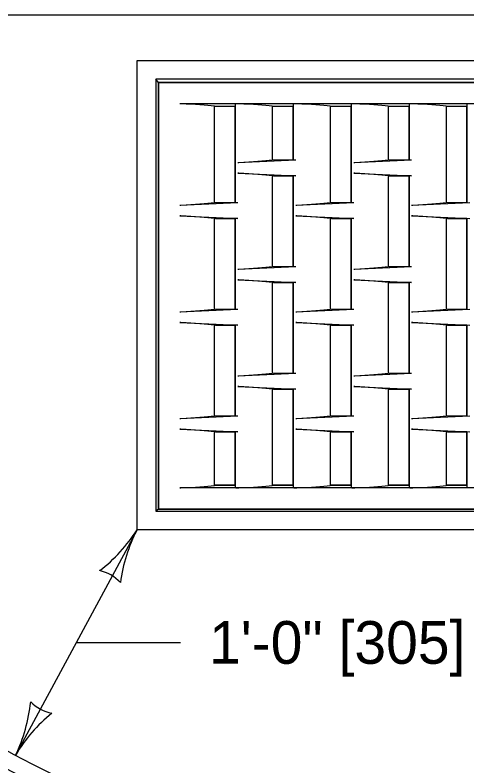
# Model space of a CAD drawing. Extents: x 49991.4 to 50021, y 49987.6 to 50011.4.
# Drawn here: x 50012.78 to 50013.415, y 49997.26 to 49998.316 of the extents above; entities that cross this region are included whole.
import ezdxf

# ---------------------------------------------------------------- set-up
doc = ezdxf.new("R2010")
doc.units = 0
for name, color, linetype in [('Level 1', 7, 'Continuous'), ('Level 18', 7, 'Continuous'), ('Level 2', 7, 'Continuous'), ('Level 3', 7, 'Continuous')]:
    doc.layers.add(name, color=color, linetype=linetype)

msp = doc.modelspace()

# ---------------------------------------------------------------- linework, layer by layer
at = {"layer": 'Level 1'}
for p, q in [((50014.5233, 49998.3155), (50012.1592, 49998.3155)), ((50012.9512, 49997.5919), (50012.9512, 49998.2518)), ((50012.9512, 49998.2518), (50013.7313, 49998.2518)), ((50012.9775, 49998.2255), (50012.9775, 49997.6182)), ((50012.9812, 49998.2207), (50012.9775, 49998.2255)), ((50013.705, 49998.2255), (50012.9775, 49998.2255)), ((50013.7013, 49998.2207), (50012.9812, 49998.2207)), ((50013.6612, 49998.1907), (50013.0112, 49998.1907)), ((50013.0599, 49998.1874), (50013.0599, 49998.0535)), ((50013.089, 49998.1869), (50013.0599, 49998.1869)), ((50013.089, 49998.1904), (50013.089, 49998.0519)), ((50013.1414, 49998.1874), (50013.1414, 49998.1869)), ((50013.1706, 49998.1869), (50013.1414, 49998.1869)), ((50013.1414, 49998.1869), (50013.1414, 49998.1135)), ((50013.1706, 49998.1904), (50013.1706, 49998.1119)), ((50013.2229, 49998.1874), (50013.2229, 49998.1869)), ((50013.2521, 49998.1869), (50013.2229, 49998.1869)), ((50013.2229, 49998.1869), (50013.2229, 49998.0535)), ((50013.2521, 49998.1904), (50013.2521, 49998.0519)), ((50013.3045, 49998.1874), (50013.3045, 49998.1869)), ((50013.3337, 49998.1869), (50013.3045, 49998.1869)), ((50013.3045, 49998.1869), (50013.3045, 49998.1135)), ((50013.3337, 49998.1904), (50013.3337, 49998.1119)), ((50013.386, 49998.1874), (50013.386, 49998.1869)), ((50013.4152, 49998.1869), (50013.386, 49998.1869)), ((50013.386, 49998.1869), (50013.386, 49998.0535)), ((50013.4152, 49998.1904), (50013.4152, 49998.0519)), ((50013.0928, 49998.1082), (50013.1743, 49998.1119)), ((50013.143, 49998.1119), (50013.1706, 49998.1119)), ((50013.2559, 49998.1082), (50013.3374, 49998.1119)), ((50013.306, 49998.1119), (50013.3337, 49998.1119)), ((50013.0928, 49998.0932), (50013.1743, 49998.0894)), ((50013.143, 49998.0894), (50013.1706, 49998.0894)), ((50013.1706, 49998.0895), (50013.1706, 49997.9619)), ((50013.2559, 49998.0932), (50013.3374, 49998.0894)), ((50013.306, 49998.0894), (50013.3337, 49998.0894)), ((50013.3337, 49998.0895), (50013.3337, 49997.9619)), ((50013.1414, 49998.0879), (50013.1414, 49997.9635)), ((50013.3045, 49998.0879), (50013.3045, 49997.9635)), ((50013.0112, 49998.0482), (50013.0928, 49998.052)), ((50013.0614, 49998.052), (50013.089, 49998.052)), ((50013.1743, 49998.0482), (50013.2559, 49998.052)), ((50013.2245, 49998.052), (50013.2521, 49998.052)), ((50013.3374, 49998.0482), (50013.419, 49998.052)), ((50013.3876, 49998.052), (50013.4152, 49998.052)), ((50013.0112, 49998.0332), (50013.0928, 49998.0295)), ((50013.0599, 49998.0279), (50013.0599, 49997.9036)), ((50013.0614, 49998.0295), (50013.089, 49998.0295)), ((50013.089, 49998.0295), (50013.089, 49997.902)), ((50013.1743, 49998.0332), (50013.2559, 49998.0295)), ((50013.2229, 49998.0279), (50013.2229, 49997.9036)), ((50013.2245, 49998.0295), (50013.2521, 49998.0295)), ((50013.2521, 49998.0295), (50013.2521, 49997.902)), ((50013.3374, 49998.0332), (50013.419, 49998.0295)), ((50013.386, 49998.0279), (50013.386, 49997.9036)), ((50013.3876, 49998.0295), (50013.4152, 49998.0295)), ((50013.4152, 49998.0295), (50013.4152, 49997.902)), ((50013.0928, 49997.9582), (50013.1743, 49997.962)), ((50013.143, 49997.962), (50013.1706, 49997.962)), ((50013.2559, 49997.9582), (50013.3374, 49997.962)), ((50013.306, 49997.962), (50013.3337, 49997.962)), ((50013.0928, 49997.9432), (50013.1743, 49997.9395)), ((50013.2559, 49997.9432), (50013.3374, 49997.9395)), ((50013.1414, 49997.9379), (50013.1414, 49997.8136)), ((50013.143, 49997.9395), (50013.1706, 49997.9395)), ((50013.1706, 49997.9395), (50013.1706, 49997.812)), ((50013.3045, 49997.9379), (50013.3045, 49997.8136)), ((50013.306, 49997.9395), (50013.3337, 49997.9395)), ((50013.3337, 49997.9395), (50013.3337, 49997.812)), ((50013.0112, 49997.8982), (50013.0928, 49997.902)), ((50013.0614, 49997.902), (50013.089, 49997.902)), ((50013.1743, 49997.8982), (50013.2559, 49997.902)), ((50013.2245, 49997.902), (50013.2521, 49997.902)), ((50013.3374, 49997.8982), (50013.419, 49997.902)), ((50013.3876, 49997.902), (50013.4152, 49997.902)), ((50013.0112, 49997.8832), (50013.0928, 49997.8795)), ((50013.0599, 49997.8779), (50013.0599, 49997.7536)), ((50013.0614, 49997.8795), (50013.089, 49997.8795)), ((50013.089, 49997.8795), (50013.089, 49997.752)), ((50013.1743, 49997.8832), (50013.2559, 49997.8795)), ((50013.2229, 49997.8779), (50013.2229, 49997.7536)), ((50013.2245, 49997.8795), (50013.2521, 49997.8795)), ((50013.2521, 49997.8795), (50013.2521, 49997.752)), ((50013.3374, 49997.8832), (50013.419, 49997.8795)), ((50013.386, 49997.8779), (50013.386, 49997.7536)), ((50013.3876, 49997.8795), (50013.4152, 49997.8795)), ((50013.4152, 49997.8795), (50013.4152, 49997.752)), ((50013.0928, 49997.8083), (50013.1743, 49997.812)), ((50013.143, 49997.812), (50013.1706, 49997.812)), ((50013.2559, 49997.8083), (50013.3374, 49997.812)), ((50013.306, 49997.812), (50013.3337, 49997.812)), ((50013.0928, 49997.7933), (50013.1743, 49997.7895)), ((50013.2559, 49997.7933), (50013.3374, 49997.7895)), ((50013.1414, 49997.788), (50013.1414, 49997.6546)), ((50013.143, 49997.7895), (50013.1706, 49997.7895)), ((50013.1706, 49997.7896), (50013.1706, 49997.6511)), ((50013.3045, 49997.788), (50013.3045, 49997.6546)), ((50013.306, 49997.7895), (50013.3337, 49997.7895)), ((50013.3337, 49997.7896), (50013.3337, 49997.6511)), ((50013.0112, 49997.7483), (50013.0928, 49997.752)), ((50013.0614, 49997.752), (50013.089, 49997.752)), ((50013.1743, 49997.7483), (50013.2559, 49997.752)), ((50013.2245, 49997.752), (50013.2521, 49997.752)), ((50013.3374, 49997.7483), (50013.419, 49997.752)), ((50013.3876, 49997.752), (50013.4152, 49997.752)), ((50013.0112, 49997.7333), (50013.0928, 49997.7295)), ((50013.0614, 49997.7295), (50013.089, 49997.7295)), ((50013.089, 49997.7296), (50013.089, 49997.6511)), ((50013.1743, 49997.7333), (50013.2559, 49997.7295)), ((50013.2245, 49997.7295), (50013.2521, 49997.7295)), ((50013.2521, 49997.7296), (50013.2521, 49997.6511)), ((50013.3374, 49997.7333), (50013.419, 49997.7295)), ((50013.3876, 49997.7295), (50013.4152, 49997.7295)), ((50013.4152, 49997.7296), (50013.4152, 49997.6511)), ((50013.0599, 49997.728), (50013.0599, 49997.6541)), ((50013.2229, 49997.728), (50013.2229, 49997.6546)), ((50013.386, 49997.728), (50013.386, 49997.6546)), ((50013.6612, 49997.6508), (50013.0112, 49997.6508)), ((50013.089, 49997.6546), (50013.0599, 49997.6546)), ((50013.1706, 49997.6546), (50013.1414, 49997.6546)), ((50013.1414, 49997.6546), (50013.1414, 49997.6541)), ((50013.2521, 49997.6546), (50013.2229, 49997.6546)), ((50013.2229, 49997.6546), (50013.2229, 49997.6541)), ((50013.3337, 49997.6546), (50013.3045, 49997.6546)), ((50013.3045, 49997.6546), (50013.3045, 49997.6541)), ((50013.4152, 49997.6546), (50013.386, 49997.6546)), ((50013.386, 49997.6546), (50013.386, 49997.6541)), ((50012.9812, 49997.6208), (50012.9775, 49997.6182)), ((50012.9775, 49997.6182), (50013.705, 49997.6182)), ((50012.9812, 49997.6208), (50013.7013, 49997.6208)), ((50013.7313, 49997.5919), (50012.9512, 49997.5919))]:
    msp.add_line(p, q, dxfattribs=at)
msp.add_lwpolyline([(50012.9812, 49998.2207), (50013.7011, 49998.2207), (50013.7011, 49997.6208), (50012.9812, 49997.6208)], close=True, dxfattribs=at)
for points in [[(50013.0599, 49998.1869), (50013.0599, 49998.0535)], [(50013.0614, 49998.052), (50013.089, 49998.052), (50013.089, 49998.1869), (50013.0599, 49998.1869)], [(50013.1706, 49998.1119), (50013.1706, 49998.1869), (50013.1414, 49998.1869), (50013.1414, 49998.1135)], [(50013.2521, 49998.052), (50013.2521, 49998.1869), (50013.2229, 49998.1869), (50013.2229, 49998.0535)], [(50013.3337, 49998.1119), (50013.3337, 49998.1869), (50013.3045, 49998.1869), (50013.3045, 49998.1135)], [(50013.4152, 49998.052), (50013.4152, 49998.1869), (50013.386, 49998.1869), (50013.386, 49998.0535)], [(50013.143, 49998.1119), (50013.1706, 49998.1119)], [(50013.306, 49998.1119), (50013.3337, 49998.1119)], [(50013.1706, 49997.962), (50013.1706, 49998.0894), (50013.143, 49998.0894)], [(50013.1414, 49998.0879), (50013.1414, 49997.9635)], [(50013.2245, 49998.052), (50013.2521, 49998.052)], [(50013.3876, 49998.052), (50013.4152, 49998.052)], [(50013.0599, 49998.0279), (50013.0599, 49997.9036)], [(50013.089, 49997.902), (50013.089, 49998.0295), (50013.0614, 49998.0295)], [(50013.2229, 49998.0279), (50013.2229, 49997.9036)], [(50013.2521, 49997.902), (50013.2521, 49998.0295), (50013.2245, 49998.0295)], [(50013.386, 49998.0279), (50013.386, 49997.9036)], [(50013.4152, 49997.902), (50013.4152, 49998.0295), (50013.3876, 49998.0295)], [(50013.143, 49997.962), (50013.1706, 49997.962)], [(50013.1414, 49997.9379), (50013.1414, 49997.8136)], [(50013.1706, 49997.812), (50013.1706, 49997.9395), (50013.143, 49997.9395)], [(50013.0614, 49997.902), (50013.089, 49997.902)], [(50013.2245, 49997.902), (50013.2521, 49997.902)], [(50013.3876, 49997.902), (50013.4152, 49997.902)], [(50013.0599, 49997.8779), (50013.0599, 49997.7536)], [(50013.089, 49997.752), (50013.089, 49997.8795), (50013.0614, 49997.8795)], [(50013.2229, 49997.8779), (50013.2229, 49997.7536)], [(50013.2521, 49997.752), (50013.2521, 49997.8795), (50013.2245, 49997.8795)], [(50013.143, 49997.812), (50013.1706, 49997.812)], [(50013.1414, 49997.788), (50013.1414, 49997.6546), (50013.1706, 49997.6546)], [(50013.1706, 49997.6546), (50013.1706, 49997.7895), (50013.143, 49997.7895)], [(50013.3045, 49997.788), (50013.3045, 49997.6546), (50013.3337, 49997.6546)], [(50013.3337, 49997.6546), (50013.3337, 49997.7895), (50013.306, 49997.7895)], [(50013.0614, 49997.752), (50013.089, 49997.752)], [(50013.2245, 49997.752), (50013.2521, 49997.752)], [(50013.2521, 49997.6546), (50013.2521, 49997.7295), (50013.2245, 49997.7295)], [(50013.2229, 49997.728), (50013.2229, 49997.6546), (50013.2521, 49997.6546)]]:
    msp.add_lwpolyline(points, dxfattribs=at)
for centre, radius, start, end in [((50013.3412, 49998.3155), 1.2045, 180, 0), ((50013.3412, 49998.3155), 1.182, 180, 0), ((50013.143, 49998.1135), 0.00156, 180, 270), ((50013.143, 49998.1135), 0.00156, 180, 270), ((50013.306, 49998.1135), 0.00156, 180, 270), ((50013.306, 49998.1135), 0.00156, 180, 270), ((50013.143, 49998.0879), 0.00156, 90, 180), ((50013.143, 49998.0879), 0.00156, 90, 180), ((50013.306, 49998.0879), 0.00156, 90, 180), ((50013.0614, 49998.0535), 0.00156, 180, 270), ((50013.0614, 49998.0535), 0.00156, 180, 270), ((50013.2245, 49998.0535), 0.00156, 180, 270), ((50013.2245, 49998.0535), 0.00156, 180, 270), ((50013.3876, 49998.0535), 0.00156, 180, 270), ((50013.3876, 49998.0535), 0.00156, 180, 270), ((50013.0614, 49998.0279), 0.00156, 90, 180), ((50013.0614, 49998.0279), 0.00156, 90, 180), ((50013.2245, 49998.0279), 0.00156, 90, 180), ((50013.2245, 49998.0279), 0.00156, 90, 180), ((50013.3876, 49998.0279), 0.00156, 90, 180), ((50013.3876, 49998.0279), 0.00156, 90, 180), ((50013.143, 49997.9635), 0.00156, 180, 270), ((50013.143, 49997.9635), 0.00156, 180, 270), ((50013.306, 49997.9635), 0.00156, 180, 270), ((50013.143, 49997.9379), 0.00156, 90, 180), ((50013.143, 49997.9379), 0.00156, 90, 180), ((50013.306, 49997.9379), 0.00156, 90, 180), ((50013.0614, 49997.9036), 0.00156, 180, 270), ((50013.0614, 49997.9036), 0.00156, 180, 270), ((50013.2245, 49997.9036), 0.00156, 180, 270), ((50013.2245, 49997.9036), 0.00156, 180, 270), ((50013.3876, 49997.9036), 0.00156, 180, 270), ((50013.3876, 49997.9036), 0.00156, 180, 270), ((50013.0614, 49997.8779), 0.00156, 90, 180), ((50013.0614, 49997.8779), 0.00156, 90, 180), ((50013.2245, 49997.8779), 0.00156, 90, 180), ((50013.2245, 49997.8779), 0.00156, 90, 180), ((50013.3876, 49997.8779), 0.00156, 90, 180), ((50013.143, 49997.8136), 0.00156, 180, 270), ((50013.143, 49997.8136), 0.00156, 180, 270), ((50013.306, 49997.8136), 0.00156, 180, 270), ((50013.143, 49997.788), 0.00156, 90, 180), ((50013.143, 49997.788), 0.00156, 90, 180), ((50013.306, 49997.788), 0.00156, 90, 180), ((50013.306, 49997.788), 0.00156, 90, 180), ((50013.0614, 49997.7536), 0.00156, 180, 270), ((50013.0614, 49997.7536), 0.00156, 180, 270), ((50013.2245, 49997.7536), 0.00156, 180, 270), ((50013.2245, 49997.7536), 0.00156, 180, 270), ((50013.3876, 49997.7536), 0.00156, 180, 270), ((50013.0614, 49997.728), 0.00156, 90, 180), ((50013.2245, 49997.728), 0.00156, 90, 180), ((50013.2245, 49997.728), 0.00156, 90, 180), ((50013.3876, 49997.728), 0.00156, 90, 180)]:
    msp.add_arc(centre, radius, start, end, dxfattribs=at)
for centre, major_axis, ratio, start_param, end_param in [((50012.9692, 49998.1833), (0.105, 0), 0.076923, 0.527586, 1.142), ((50013.0928, 49998.1904), (0.00375, 0), 0.076923, 1.570796, 3.141593), ((50013.0928, 49998.1904), (0.00375, 0), 0.076923, 1.142, 1.570796), ((50013.0507, 49998.1833), (0.105, 0), 0.076923, 0.527586, 1.142), ((50013.1743, 49998.1904), (0.00375, 0), 0.076923, 1.570796, 3.141593), ((50013.1743, 49998.1904), (0.00375, 0), 0.076923, 1.142, 1.570796), ((50013.1322, 49998.1833), (0.105, 0), 0.076923, 0.527586, 1.142), ((50013.2559, 49998.1904), (0.00375, 0), 0.076923, 1.570796, 3.141593), ((50013.2559, 49998.1904), (0.00375, 0), 0.076923, 1.142, 1.570796), ((50013.2138, 49998.1833), (0.105, 0), 0.076923, 0.527586, 1.142), ((50013.3374, 49998.1904), (0.00375, 0), 0.076923, 1.570796, 3.141593), ((50013.3374, 49998.1904), (0.00375, 0), 0.076923, 1.142, 1.570796), ((50013.2953, 49998.1833), (0.105, 0), 0.076923, 0.527586, 1.142), ((50013.0507, 49998.1097), (-0.105, -0.0048), 0.035758, 1.997966, 2.612379), ((50013.1743, 49998.1121), (-0.00375, -0.00017), 0.035758, 6.281558, 7.852354), ((50013.2138, 49998.1097), (-0.105, -0.0048), 0.035758, 1.997966, 2.612379), ((50013.3374, 49998.1121), (-0.00375, -0.00017), 0.035758, 6.281558, 7.852354), ((50013.2559, 49998.1083), (-0.00375, -0.00017), 0.035758, 1.569169, 1.997966), ((50013.0507, 49998.0917), (0.105, -0.0048), 0.035758, 0.529214, 1.143627), ((50013.1743, 49998.0893), (0.00375, -0.00017), 0.035758, 1.572424, 3.14322), ((50013.2559, 49998.0931), (0.00375, -0.00017), 0.035758, 1.143627, 1.572424), ((50013.2138, 49998.0917), (0.105, -0.0048), 0.035758, 0.529214, 1.143627), ((50013.3374, 49998.0893), (0.00375, -0.00017), 0.035758, 1.572424, 3.14322), ((50013.0112, 49998.0483), (-0.00375, -0.00017), 0.035758, 1.569169, 1.997966), ((50012.9692, 49998.0497), (-0.105, -0.0048), 0.035758, 1.997966, 2.612379), ((50013.0928, 49998.0521), (-0.00375, -0.00017), 0.035758, 6.281558, 7.852354), ((50013.1322, 49998.0497), (-0.105, -0.0048), 0.035758, 1.997966, 2.612379), ((50013.2559, 49998.0521), (-0.00375, -0.00017), 0.035758, 6.281558, 7.852354), ((50013.2953, 49998.0497), (-0.105, -0.0048), 0.035758, 1.997966, 2.612379), ((50013.0112, 49998.0331), (0.00375, -0.00017), 0.035758, 1.143627, 1.572424), ((50012.9692, 49998.0317), (0.105, -0.0048), 0.035758, 0.529214, 1.143627), ((50013.0928, 49998.0293), (0.00375, -0.00017), 0.035758, 1.572424, 3.14322), ((50013.1322, 49998.0317), (0.105, -0.0048), 0.035758, 0.529214, 1.143627), ((50013.2559, 49998.0293), (0.00375, -0.00017), 0.035758, 1.572424, 3.14322), ((50013.2953, 49998.0317), (0.105, -0.0048), 0.035758, 0.529214, 1.143627), ((50013.0507, 49997.9598), (-0.105, -0.0048), 0.035758, 1.997966, 2.612379), ((50013.1743, 49997.9621), (-0.00375, -0.00017), 0.035758, 6.281558, 7.852354), ((50013.2138, 49997.9598), (-0.105, -0.0048), 0.035758, 1.997966, 2.612379), ((50013.3374, 49997.9621), (-0.00375, -0.00017), 0.035758, 6.281558, 7.852354), ((50013.2559, 49997.9584), (-0.00375, -0.00017), 0.035758, 1.569169, 1.997966), ((50013.0507, 49997.9417), (0.105, -0.0048), 0.035758, 0.529214, 1.143627), ((50013.2559, 49997.9431), (0.00375, -0.00017), 0.035758, 1.143627, 1.572424), ((50013.2138, 49997.9417), (0.105, -0.0048), 0.035758, 0.529214, 1.143627), ((50013.1743, 49997.9394), (0.00375, -0.00017), 0.035758, 1.572424, 3.14322), ((50013.3374, 49997.9394), (0.00375, -0.00017), 0.035758, 1.572424, 3.14322), ((50012.9692, 49997.8998), (-0.105, -0.0048), 0.035758, 1.997966, 2.612379), ((50013.0928, 49997.9021), (-0.00375, -0.00017), 0.035758, 6.281558, 7.852354), ((50013.1322, 49997.8998), (-0.105, -0.0048), 0.035758, 1.997966, 2.612379), ((50013.2559, 49997.9021), (-0.00375, -0.00017), 0.035758, 6.281558, 7.852354), ((50013.2953, 49997.8998), (-0.105, -0.0048), 0.035758, 1.997966, 2.612379), ((50012.9692, 49997.8817), (0.105, -0.0048), 0.035758, 0.529214, 1.143627), ((50013.0928, 49997.8794), (0.00375, -0.00017), 0.035758, 1.572424, 3.14322), ((50013.1322, 49997.8817), (0.105, -0.0048), 0.035758, 0.529214, 1.143627), ((50013.2559, 49997.8794), (0.00375, -0.00017), 0.035758, 1.572424, 3.14322), ((50013.2953, 49997.8817), (0.105, -0.0048), 0.035758, 0.529214, 1.143627), ((50013.0507, 49997.8098), (-0.105, -0.0048), 0.035758, 1.997966, 2.612379), ((50013.1743, 49997.8122), (-0.00375, -0.00017), 0.035758, 6.281558, 7.852354), ((50013.2559, 49997.8084), (-0.00375, -0.00017), 0.035758, 1.569169, 1.997966), ((50013.2138, 49997.8098), (-0.105, -0.0048), 0.035758, 1.997966, 2.612379), ((50013.3374, 49997.8122), (-0.00375, -0.00017), 0.035758, 6.281558, 7.852354), ((50013.0507, 49997.7918), (0.105, -0.0048), 0.035758, 0.529214, 1.143627), ((50013.2559, 49997.7931), (0.00375, -0.00017), 0.035758, 1.143627, 1.572424), ((50013.2138, 49997.7918), (0.105, -0.0048), 0.035758, 0.529214, 1.143627), ((50013.1743, 49997.7894), (0.00375, -0.00017), 0.035758, 1.572424, 3.14322), ((50013.3374, 49997.7894), (0.00375, -0.00017), 0.035758, 1.572424, 3.14322), ((50012.9692, 49997.7498), (-0.105, -0.0048), 0.035758, 1.997966, 2.612379), ((50013.0928, 49997.7522), (-0.00375, -0.00017), 0.035758, 6.281558, 7.852354), ((50013.1322, 49997.7498), (-0.105, -0.0048), 0.035758, 1.997966, 2.612379), ((50013.2559, 49997.7522), (-0.00375, -0.00017), 0.035758, 6.281558, 7.852354), ((50013.2953, 49997.7498), (-0.105, -0.0048), 0.035758, 1.997966, 2.612379), ((50012.9692, 49997.7318), (0.105, -0.0048), 0.035758, 0.529214, 1.143627), ((50013.0928, 49997.7294), (0.00375, -0.00017), 0.035758, 1.572424, 3.14322), ((50013.1322, 49997.7318), (0.105, -0.0048), 0.035758, 0.529214, 1.143627), ((50013.2559, 49997.7294), (0.00375, -0.00017), 0.035758, 1.572424, 3.14322), ((50013.2953, 49997.7318), (0.105, -0.0048), 0.035758, 0.529214, 1.143627), ((50012.9692, 49997.6582), (0.105, 0), 0.076923, 5.141186, 5.755599), ((50013.0928, 49997.6511), (0.00375, 0), 0.076923, 3.141593, 4.712389), ((50013.0928, 49997.6511), (0.00375, 0), 0.076923, 4.712389, 5.141186), ((50013.0507, 49997.6582), (0.105, 0), 0.076923, 5.141186, 5.755599), ((50013.1743, 49997.6511), (0.00375, 0), 0.076923, 3.141593, 4.712389), ((50013.1743, 49997.6511), (0.00375, 0), 0.076923, 4.712389, 5.141186), ((50013.1322, 49997.6582), (0.105, 0), 0.076923, 5.141186, 5.755599), ((50013.2559, 49997.6511), (0.00375, 0), 0.076923, 3.141593, 4.712389), ((50013.2559, 49997.6511), (0.00375, 0), 0.076923, 4.712389, 5.141186), ((50013.2138, 49997.6582), (0.105, 0), 0.076923, 5.141186, 5.755599), ((50013.3374, 49997.6511), (0.00375, 0), 0.076923, 3.141593, 4.712389), ((50013.3374, 49997.6511), (0.00375, 0), 0.076923, 4.712389, 5.141186), ((50013.2953, 49997.6582), (0.105, 0), 0.076923, 5.141186, 5.755599)]:
    msp.add_ellipse(centre, major_axis=major_axis, ratio=ratio, start_param=start_param, end_param=end_param, dxfattribs=at)
at = {"layer": 'Level 18'}
for p, q in [((50012.9812, 49998.2207), (50012.9812, 49997.6208)), ((50012.9512, 49997.5919), (50012.9512, 49997.5919)), ((50012.9512, 49997.5919), (50012.9512, 49997.5919))]:
    msp.add_line(p, q, dxfattribs=at)
for points in [[(50013.3337, 49997.962), (50013.3337, 49998.0894), (50013.306, 49998.0894)], [(50013.3045, 49998.0879), (50013.3045, 49997.9635)], [(50013.306, 49997.962), (50013.3337, 49997.962)], [(50013.3045, 49997.9379), (50013.3045, 49997.8136)], [(50013.3337, 49997.812), (50013.3337, 49997.9395), (50013.306, 49997.9395)], [(50013.386, 49997.8779), (50013.386, 49997.7536)], [(50013.4152, 49997.752), (50013.4152, 49997.8795), (50013.3876, 49997.8795)], [(50013.306, 49997.812), (50013.3337, 49997.812)], [(50013.3876, 49997.752), (50013.4152, 49997.752)], [(50013.089, 49997.6546), (50013.089, 49997.7295), (50013.0614, 49997.7295)], [(50013.4152, 49997.6546), (50013.4152, 49997.7295), (50013.3876, 49997.7295)], [(50013.0599, 49997.728), (50013.0599, 49997.6546), (50013.089, 49997.6546)], [(50013.386, 49997.728), (50013.386, 49997.6546), (50013.4152, 49997.6546)]]:
    msp.add_lwpolyline(points, dxfattribs=at)
for centre, start, end in [((50013.306, 49998.0879), 90, 180), ((50013.306, 49997.9635), 180, 270), ((50013.306, 49997.9379), 90, 180), ((50013.3876, 49997.8779), 90, 180), ((50013.306, 49997.8136), 180, 270), ((50013.3876, 49997.7536), 180, 270), ((50013.0614, 49997.728), 90, 180), ((50013.3876, 49997.728), 90, 180)]:
    msp.add_arc(centre, 0.00156, start, end, dxfattribs=at)
for centre, major_axis, ratio, start_param, end_param in [((50013.0112, 49998.1904), (0.00375, 0), 0.076923, 1.142, 1.570796), ((50013.0928, 49998.1083), (-0.00375, -0.00017), 0.035758, 1.569169, 1.997966), ((50013.0928, 49998.0931), (0.00375, -0.00017), 0.035758, 1.143627, 1.572424), ((50013.1743, 49998.0483), (-0.00375, -0.00017), 0.035758, 1.569169, 1.997966), ((50013.3374, 49998.0483), (-0.00375, -0.00017), 0.035758, 1.569169, 1.997966), ((50013.1743, 49998.0331), (0.00375, -0.00017), 0.035758, 1.143627, 1.572424), ((50013.3374, 49998.0331), (0.00375, -0.00017), 0.035758, 1.143627, 1.572424), ((50013.0928, 49997.9584), (-0.00375, -0.00017), 0.035758, 1.569169, 1.997966), ((50013.0928, 49997.9431), (0.00375, -0.00017), 0.035758, 1.143627, 1.572424), ((50013.0112, 49997.8984), (-0.00375, -0.00017), 0.035758, 1.569169, 1.997966), ((50013.1743, 49997.8984), (-0.00375, -0.00017), 0.035758, 1.569169, 1.997966), ((50013.3374, 49997.8984), (-0.00375, -0.00017), 0.035758, 1.569169, 1.997966), ((50013.0112, 49997.8831), (0.00375, -0.00017), 0.035758, 1.143627, 1.572424), ((50013.1743, 49997.8831), (0.00375, -0.00017), 0.035758, 1.143627, 1.572424), ((50013.3374, 49997.8831), (0.00375, -0.00017), 0.035758, 1.143627, 1.572424), ((50013.0928, 49997.8084), (-0.00375, -0.00017), 0.035758, 1.569169, 1.997966), ((50013.0928, 49997.7931), (0.00375, -0.00017), 0.035758, 1.143627, 1.572424), ((50013.0112, 49997.7484), (-0.00375, -0.00017), 0.035758, 1.569169, 1.997966), ((50013.1743, 49997.7484), (-0.00375, -0.00017), 0.035758, 1.569169, 1.997966), ((50013.3374, 49997.7484), (-0.00375, -0.00017), 0.035758, 1.569169, 1.997966), ((50013.0112, 49997.7332), (0.00375, -0.00017), 0.035758, 1.143627, 1.572424), ((50013.1743, 49997.7332), (0.00375, -0.00017), 0.035758, 1.143627, 1.572424), ((50013.3374, 49997.7332), (0.00375, -0.00017), 0.035758, 1.143627, 1.572424), ((50013.0112, 49997.6511), (0.00375, 0), 0.076923, 4.712389, 5.141186)]:
    msp.add_ellipse(centre, major_axis=major_axis, ratio=ratio, start_param=start_param, end_param=end_param, dxfattribs=at)
at = {"layer": 'Level 3'}
for p, q in [((50012.9512, 49997.5919), (50012.7804, 49997.275)), ((50012.8658, 49997.4335), (50013.0125, 49997.4335))]:
    msp.add_line(p, q, dxfattribs=at)
for centre, radius, start, end in [((50012.7635, 49997.7109), 0.2223, 307.456, 327.6395), ((50013.1585, 49997.4855), 0.233, 152.8273, 172.0772), ((50012.8871, 49997.4809), 0.0548, 42.1388, 77.8612), ((50012.5701, 49997.3753), 0.233, 334.5036, 353.7534), ((50012.8413, 49997.3879), 0.0548, 223.8151, 259.5374), ((50012.9716, 49997.1616), 0.2223, 129.1323, 149.3158)]:
    msp.add_arc(centre, radius, start, end, dxfattribs=at)

# ---------------------------------------------------------------- texts
at = {"layer": 'Level 2'}
msp.add_text('1\'-0" [305]', height=0.06, dxfattribs=at).set_placement((50013.0525, 49997.4035))

doc.saveas('drawing.dxf')
